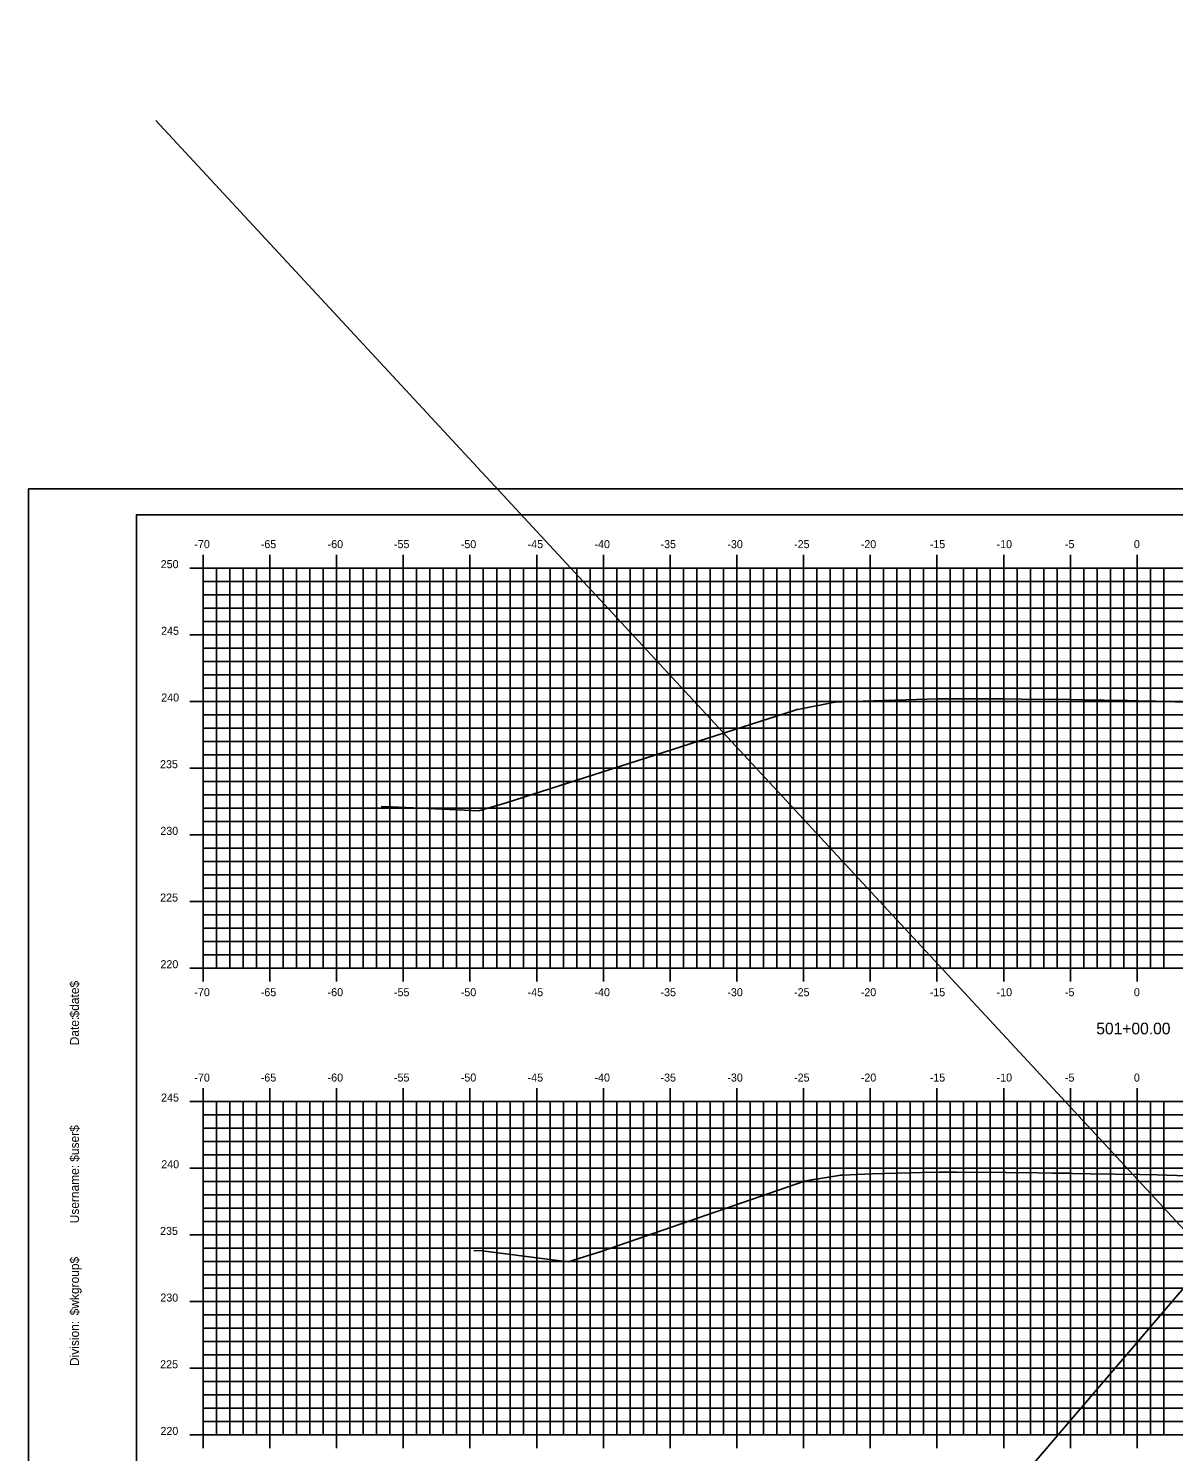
# Model space of a CAD drawing. Extents: x 1170543 to 1177585, y 609599 to 610623.
# Drawn here: x 1170543.4 to 1170629.2, y 610306.6 to 610413.3 of the extents above; entities that cross this region are included whole.
import ezdxf

# ---------------------------------------------------------------- set-up
doc = ezdxf.new("R2010")
doc.units = 0
doc.layers.add('Default', color=7, linetype='Continuous')

msp = doc.modelspace()

# ---------------------------------------------------------------- linework, layer by layer
at = {"layer": 'Default'}
for p, q in [((1170710.72, 610413.27), (1170567.59, 610245.89)), ((1170552.93, 610406.37), (1170706.4, 610240.71)), ((1170556.47, 610373.8), (1170556.47, 610372.8)), ((1170561.47, 610373.8), (1170561.47, 610372.8)), ((1170566.47, 610373.8), (1170566.47, 610372.8)), ((1170571.47, 610373.8), (1170571.47, 610372.8)), ((1170576.47, 610373.8), (1170576.47, 610372.8)), ((1170581.47, 610373.8), (1170581.47, 610372.8)), ((1170586.47, 610373.8), (1170586.47, 610372.8)), ((1170591.47, 610373.8), (1170591.47, 610372.8)), ((1170596.47, 610373.8), (1170596.47, 610372.8)), ((1170601.47, 610373.8), (1170601.47, 610372.8)), ((1170606.47, 610373.8), (1170606.47, 610372.8)), ((1170611.47, 610373.8), (1170611.47, 610372.8)), ((1170616.47, 610373.8), (1170616.47, 610372.8)), ((1170621.47, 610373.8), (1170621.47, 610372.8)), ((1170626.47, 610373.8), (1170626.47, 610372.8)), ((1170555.47, 610372.8), (1170556.47, 610372.8)), ((1170556.47, 610372.8), (1170696.47, 610372.8)), ((1170556.47, 610342.8), (1170556.47, 610372.8)), ((1170556.47, 610342.8), (1170556.47, 610372.8)), ((1170556.47, 610372.8), (1170696.47, 610372.8)), ((1170557.47, 610342.8), (1170557.47, 610372.8)), ((1170558.47, 610342.8), (1170558.47, 610372.8)), ((1170559.47, 610342.8), (1170559.47, 610372.8)), ((1170560.47, 610342.8), (1170560.47, 610372.8)), ((1170561.47, 610342.8), (1170561.47, 610372.8)), ((1170562.47, 610342.8), (1170562.47, 610372.8)), ((1170563.47, 610342.8), (1170563.47, 610372.8)), ((1170564.47, 610342.8), (1170564.47, 610372.8)), ((1170565.47, 610342.8), (1170565.47, 610372.8)), ((1170566.47, 610342.8), (1170566.47, 610372.8)), ((1170567.47, 610342.8), (1170567.47, 610372.8)), ((1170568.47, 610342.8), (1170568.47, 610372.8)), ((1170569.47, 610342.8), (1170569.47, 610372.8)), ((1170570.47, 610342.8), (1170570.47, 610372.8)), ((1170571.47, 610342.8), (1170571.47, 610372.8)), ((1170572.47, 610342.8), (1170572.47, 610372.8)), ((1170573.47, 610342.8), (1170573.47, 610372.8)), ((1170574.47, 610342.8), (1170574.47, 610372.8)), ((1170575.47, 610342.8), (1170575.47, 610372.8)), ((1170576.47, 610342.8), (1170576.47, 610372.8)), ((1170577.47, 610342.8), (1170577.47, 610372.8)), ((1170578.47, 610342.8), (1170578.47, 610372.8)), ((1170579.47, 610342.8), (1170579.47, 610372.8)), ((1170580.47, 610342.8), (1170580.47, 610372.8)), ((1170581.47, 610342.8), (1170581.47, 610372.8)), ((1170582.47, 610342.8), (1170582.47, 610372.8)), ((1170583.47, 610342.8), (1170583.47, 610372.8)), ((1170584.47, 610342.8), (1170584.47, 610372.8)), ((1170585.47, 610342.8), (1170585.47, 610372.8)), ((1170586.47, 610342.8), (1170586.47, 610372.8)), ((1170587.47, 610342.8), (1170587.47, 610372.8)), ((1170588.47, 610342.8), (1170588.47, 610372.8)), ((1170589.47, 610342.8), (1170589.47, 610372.8)), ((1170590.47, 610342.8), (1170590.47, 610372.8)), ((1170591.47, 610342.8), (1170591.47, 610372.8)), ((1170592.47, 610342.8), (1170592.47, 610372.8)), ((1170593.47, 610342.8), (1170593.47, 610372.8)), ((1170594.47, 610342.8), (1170594.47, 610372.8)), ((1170595.47, 610342.8), (1170595.47, 610372.8)), ((1170596.47, 610342.8), (1170596.47, 610372.8)), ((1170597.47, 610342.8), (1170597.47, 610372.8)), ((1170598.47, 610342.8), (1170598.47, 610372.8)), ((1170599.47, 610342.8), (1170599.47, 610372.8)), ((1170600.47, 610342.8), (1170600.47, 610372.8)), ((1170601.47, 610342.8), (1170601.47, 610372.8)), ((1170602.47, 610342.8), (1170602.47, 610372.8)), ((1170603.47, 610342.8), (1170603.47, 610372.8)), ((1170604.47, 610342.8), (1170604.47, 610372.8)), ((1170605.47, 610342.8), (1170605.47, 610372.8)), ((1170606.47, 610342.8), (1170606.47, 610372.8)), ((1170607.47, 610342.8), (1170607.47, 610372.8)), ((1170608.47, 610342.8), (1170608.47, 610372.8)), ((1170609.47, 610342.8), (1170609.47, 610372.8)), ((1170610.47, 610342.8), (1170610.47, 610372.8)), ((1170611.47, 610342.8), (1170611.47, 610372.8)), ((1170612.47, 610342.8), (1170612.47, 610372.8)), ((1170613.47, 610342.8), (1170613.47, 610372.8)), ((1170614.47, 610342.8), (1170614.47, 610372.8)), ((1170615.47, 610342.8), (1170615.47, 610372.8)), ((1170616.47, 610342.8), (1170616.47, 610372.8)), ((1170617.47, 610342.8), (1170617.47, 610372.8)), ((1170618.47, 610342.8), (1170618.47, 610372.8)), ((1170619.47, 610342.8), (1170619.47, 610372.8)), ((1170620.47, 610342.8), (1170620.47, 610372.8)), ((1170621.47, 610342.8), (1170621.47, 610372.8)), ((1170622.47, 610342.8), (1170622.47, 610372.8)), ((1170623.47, 610342.8), (1170623.47, 610372.8)), ((1170624.47, 610342.8), (1170624.47, 610372.8)), ((1170625.47, 610342.8), (1170625.47, 610372.8)), ((1170626.47, 610342.8), (1170626.47, 610372.8)), ((1170627.47, 610342.8), (1170627.47, 610372.8)), ((1170628.47, 610342.8), (1170628.47, 610372.8)), ((1170556.47, 610371.8), (1170696.47, 610371.8)), ((1170556.47, 610371.8), (1170557.47, 610371.8)), ((1170556.47, 610370.8), (1170696.47, 610370.8)), ((1170556.47, 610370.8), (1170557.47, 610370.8)), ((1170556.47, 610369.8), (1170696.47, 610369.8)), ((1170556.47, 610369.8), (1170557.47, 610369.8)), ((1170556.47, 610368.8), (1170696.47, 610368.8)), ((1170556.47, 610368.8), (1170557.47, 610368.8)), ((1170555.47, 610367.8), (1170556.47, 610367.8)), ((1170556.47, 610367.8), (1170696.47, 610367.8)), ((1170556.47, 610366.8), (1170696.47, 610366.8)), ((1170556.47, 610366.8), (1170557.47, 610366.8)), ((1170556.47, 610365.8), (1170696.47, 610365.8)), ((1170556.47, 610365.8), (1170557.47, 610365.8)), ((1170556.47, 610364.8), (1170696.47, 610364.8)), ((1170556.47, 610364.8), (1170557.47, 610364.8)), ((1170556.47, 610363.8), (1170696.47, 610363.8)), ((1170556.47, 610363.8), (1170557.47, 610363.8)), ((1170555.47, 610362.8), (1170556.47, 610362.8)), ((1170556.47, 610362.8), (1170696.47, 610362.8)), ((1170556.47, 610361.8), (1170696.47, 610361.8)), ((1170556.47, 610361.8), (1170557.47, 610361.8)), ((1170556.47, 610360.8), (1170696.47, 610360.8)), ((1170556.47, 610360.8), (1170557.47, 610360.8)), ((1170556.47, 610359.8), (1170696.47, 610359.8)), ((1170556.47, 610359.8), (1170557.47, 610359.8)), ((1170556.47, 610358.8), (1170696.47, 610358.8)), ((1170556.47, 610358.8), (1170557.47, 610358.8)), ((1170555.47, 610357.8), (1170556.47, 610357.8)), ((1170556.47, 610357.8), (1170696.47, 610357.8)), ((1170556.47, 610356.8), (1170696.47, 610356.8)), ((1170556.47, 610356.8), (1170557.47, 610356.8)), ((1170556.47, 610355.8), (1170696.47, 610355.8)), ((1170556.47, 610355.8), (1170557.47, 610355.8)), ((1170556.47, 610354.8), (1170696.47, 610354.8)), ((1170556.47, 610354.8), (1170557.47, 610354.8)), ((1170556.47, 610353.8), (1170696.47, 610353.8)), ((1170556.47, 610353.8), (1170557.47, 610353.8)), ((1170555.47, 610352.8), (1170556.47, 610352.8)), ((1170556.47, 610352.8), (1170696.47, 610352.8)), ((1170556.47, 610351.8), (1170696.47, 610351.8)), ((1170556.47, 610351.8), (1170557.47, 610351.8)), ((1170556.47, 610350.8), (1170696.47, 610350.8)), ((1170556.47, 610350.8), (1170557.47, 610350.8)), ((1170556.47, 610349.8), (1170696.47, 610349.8)), ((1170556.47, 610349.8), (1170557.47, 610349.8)), ((1170555.47, 610347.8), (1170556.47, 610347.8)), ((1170556.47, 610348.8), (1170696.47, 610348.8)), ((1170556.47, 610348.8), (1170557.47, 610348.8)), ((1170556.47, 610347.8), (1170696.47, 610347.8)), ((1170556.47, 610346.8), (1170696.47, 610346.8)), ((1170556.47, 610346.8), (1170557.47, 610346.8)), ((1170556.47, 610345.8), (1170696.47, 610345.8)), ((1170556.47, 610345.8), (1170557.47, 610345.8)), ((1170556.47, 610344.8), (1170696.47, 610344.8)), ((1170556.47, 610344.8), (1170557.47, 610344.8)), ((1170556.47, 610343.8), (1170696.47, 610343.8)), ((1170556.47, 610343.8), (1170557.47, 610343.8)), ((1170555.47, 610342.8), (1170556.47, 610342.8)), ((1170556.47, 610342.8), (1170696.47, 610342.8)), ((1170556.47, 610342.8), (1170696.47, 610342.8)), ((1170556.47, 610341.8), (1170556.47, 610342.8)), ((1170561.47, 610341.8), (1170561.47, 610342.8)), ((1170566.47, 610341.8), (1170566.47, 610342.8)), ((1170571.47, 610341.8), (1170571.47, 610342.8)), ((1170576.47, 610341.8), (1170576.47, 610342.8)), ((1170581.47, 610341.8), (1170581.47, 610342.8)), ((1170586.47, 610341.8), (1170586.47, 610342.8)), ((1170591.47, 610341.8), (1170591.47, 610342.8)), ((1170596.47, 610341.8), (1170596.47, 610342.8)), ((1170601.47, 610341.8), (1170601.47, 610342.8)), ((1170606.47, 610341.8), (1170606.47, 610342.8)), ((1170611.47, 610341.8), (1170611.47, 610342.8)), ((1170616.47, 610341.8), (1170616.47, 610342.8)), ((1170621.47, 610341.8), (1170621.47, 610342.8)), ((1170626.47, 610341.8), (1170626.47, 610342.8)), ((1170556.47, 610333.8), (1170556.47, 610332.8)), ((1170561.47, 610333.8), (1170561.47, 610332.8)), ((1170566.47, 610333.8), (1170566.47, 610332.8)), ((1170571.47, 610333.8), (1170571.47, 610332.8)), ((1170576.47, 610333.8), (1170576.47, 610332.8)), ((1170581.47, 610333.8), (1170581.47, 610332.8)), ((1170586.47, 610333.8), (1170586.47, 610332.8)), ((1170591.47, 610333.8), (1170591.47, 610332.8)), ((1170596.47, 610333.8), (1170596.47, 610332.8)), ((1170601.47, 610333.8), (1170601.47, 610332.8)), ((1170606.47, 610333.8), (1170606.47, 610332.8)), ((1170611.47, 610333.8), (1170611.47, 610332.8)), ((1170616.47, 610333.8), (1170616.47, 610332.8)), ((1170621.47, 610333.8), (1170621.47, 610332.8)), ((1170626.47, 610333.8), (1170626.47, 610332.8)), ((1170555.47, 610332.8), (1170556.47, 610332.8)), ((1170556.47, 610332.8), (1170696.47, 610332.8)), ((1170556.47, 610307.8), (1170556.47, 610332.8)), ((1170556.47, 610307.8), (1170556.47, 610332.8)), ((1170556.47, 610332.8), (1170696.47, 610332.8)), ((1170556.47, 610331.8), (1170696.47, 610331.8)), ((1170556.47, 610331.8), (1170557.47, 610331.8)), ((1170557.47, 610307.8), (1170557.47, 610332.8)), ((1170558.47, 610307.8), (1170558.47, 610332.8)), ((1170559.47, 610307.8), (1170559.47, 610332.8)), ((1170560.47, 610307.8), (1170560.47, 610332.8)), ((1170561.47, 610307.8), (1170561.47, 610332.8)), ((1170562.47, 610307.8), (1170562.47, 610332.8)), ((1170563.47, 610307.8), (1170563.47, 610332.8)), ((1170564.47, 610307.8), (1170564.47, 610332.8)), ((1170565.47, 610307.8), (1170565.47, 610332.8)), ((1170566.47, 610307.8), (1170566.47, 610332.8)), ((1170567.47, 610307.8), (1170567.47, 610332.8)), ((1170568.47, 610307.8), (1170568.47, 610332.8)), ((1170569.47, 610307.8), (1170569.47, 610332.8)), ((1170570.47, 610307.8), (1170570.47, 610332.8)), ((1170571.47, 610307.8), (1170571.47, 610332.8)), ((1170572.47, 610307.8), (1170572.47, 610332.8)), ((1170573.47, 610307.8), (1170573.47, 610332.8)), ((1170574.47, 610307.8), (1170574.47, 610332.8)), ((1170575.47, 610307.8), (1170575.47, 610332.8)), ((1170576.47, 610307.8), (1170576.47, 610332.8)), ((1170577.47, 610307.8), (1170577.47, 610332.8)), ((1170578.47, 610307.8), (1170578.47, 610332.8)), ((1170579.47, 610307.8), (1170579.47, 610332.8)), ((1170580.47, 610307.8), (1170580.47, 610332.8)), ((1170581.47, 610307.8), (1170581.47, 610332.8)), ((1170582.47, 610307.8), (1170582.47, 610332.8)), ((1170583.47, 610307.8), (1170583.47, 610332.8)), ((1170584.47, 610307.8), (1170584.47, 610332.8)), ((1170585.47, 610307.8), (1170585.47, 610332.8)), ((1170586.47, 610307.8), (1170586.47, 610332.8)), ((1170587.47, 610307.8), (1170587.47, 610332.8)), ((1170588.47, 610307.8), (1170588.47, 610332.8)), ((1170589.47, 610307.8), (1170589.47, 610332.8)), ((1170590.47, 610307.8), (1170590.47, 610332.8)), ((1170591.47, 610307.8), (1170591.47, 610332.8)), ((1170592.47, 610307.8), (1170592.47, 610332.8)), ((1170593.47, 610307.8), (1170593.47, 610332.8)), ((1170594.47, 610307.8), (1170594.47, 610332.8)), ((1170595.47, 610307.8), (1170595.47, 610332.8)), ((1170596.47, 610307.8), (1170596.47, 610332.8)), ((1170597.47, 610307.8), (1170597.47, 610332.8)), ((1170598.47, 610307.8), (1170598.47, 610332.8)), ((1170599.47, 610307.8), (1170599.47, 610332.8)), ((1170600.47, 610307.8), (1170600.47, 610332.8)), ((1170601.47, 610307.8), (1170601.47, 610332.8)), ((1170602.47, 610307.8), (1170602.47, 610332.8)), ((1170603.47, 610307.8), (1170603.47, 610332.8)), ((1170604.47, 610307.8), (1170604.47, 610332.8)), ((1170605.47, 610307.8), (1170605.47, 610332.8)), ((1170606.47, 610307.8), (1170606.47, 610332.8)), ((1170607.47, 610307.8), (1170607.47, 610332.8)), ((1170608.47, 610307.8), (1170608.47, 610332.8)), ((1170609.47, 610307.8), (1170609.47, 610332.8)), ((1170610.47, 610307.8), (1170610.47, 610332.8)), ((1170611.47, 610307.8), (1170611.47, 610332.8)), ((1170612.47, 610307.8), (1170612.47, 610332.8)), ((1170613.47, 610307.8), (1170613.47, 610332.8)), ((1170614.47, 610307.8), (1170614.47, 610332.8)), ((1170615.47, 610307.8), (1170615.47, 610332.8)), ((1170616.47, 610307.8), (1170616.47, 610332.8)), ((1170617.47, 610307.8), (1170617.47, 610332.8)), ((1170618.47, 610307.8), (1170618.47, 610332.8)), ((1170619.47, 610307.8), (1170619.47, 610332.8)), ((1170620.47, 610307.8), (1170620.47, 610332.8)), ((1170621.47, 610307.8), (1170621.47, 610332.8)), ((1170622.47, 610307.8), (1170622.47, 610332.8)), ((1170623.47, 610307.8), (1170623.47, 610332.8)), ((1170624.47, 610307.8), (1170624.47, 610332.8)), ((1170625.47, 610307.8), (1170625.47, 610332.8)), ((1170626.47, 610307.8), (1170626.47, 610332.8)), ((1170627.47, 610307.8), (1170627.47, 610332.8)), ((1170628.47, 610307.8), (1170628.47, 610332.8)), ((1170556.47, 610330.8), (1170696.47, 610330.8)), ((1170556.47, 610330.8), (1170557.47, 610330.8)), ((1170556.47, 610329.8), (1170696.47, 610329.8)), ((1170556.47, 610329.8), (1170557.47, 610329.8)), ((1170556.47, 610328.8), (1170696.47, 610328.8)), ((1170556.47, 610328.8), (1170557.47, 610328.8)), ((1170555.47, 610327.8), (1170556.47, 610327.8)), ((1170556.47, 610327.8), (1170696.47, 610327.8)), ((1170556.47, 610326.8), (1170696.47, 610326.8)), ((1170556.47, 610326.8), (1170557.47, 610326.8)), ((1170556.47, 610325.8), (1170696.47, 610325.8)), ((1170556.47, 610325.8), (1170557.47, 610325.8)), ((1170556.47, 610324.8), (1170696.47, 610324.8)), ((1170556.47, 610324.8), (1170557.47, 610324.8)), ((1170556.47, 610323.8), (1170696.47, 610323.8)), ((1170556.47, 610323.8), (1170557.47, 610323.8)), ((1170555.47, 610322.8), (1170556.47, 610322.8)), ((1170556.47, 610322.8), (1170696.47, 610322.8)), ((1170556.47, 610321.8), (1170696.47, 610321.8)), ((1170556.47, 610321.8), (1170557.47, 610321.8)), ((1170556.47, 610320.8), (1170696.47, 610320.8)), ((1170556.47, 610320.8), (1170557.47, 610320.8)), ((1170556.47, 610319.8), (1170696.47, 610319.8)), ((1170556.47, 610319.8), (1170557.47, 610319.8)), ((1170556.47, 610318.8), (1170696.47, 610318.8)), ((1170556.47, 610318.8), (1170557.47, 610318.8)), ((1170555.47, 610317.8), (1170556.47, 610317.8)), ((1170556.47, 610317.8), (1170696.47, 610317.8)), ((1170556.47, 610316.8), (1170696.47, 610316.8)), ((1170556.47, 610316.8), (1170557.47, 610316.8)), ((1170556.47, 610315.8), (1170696.47, 610315.8)), ((1170556.47, 610315.8), (1170557.47, 610315.8)), ((1170556.47, 610314.8), (1170696.47, 610314.8)), ((1170556.47, 610314.8), (1170557.47, 610314.8)), ((1170556.47, 610313.8), (1170696.47, 610313.8)), ((1170556.47, 610313.8), (1170557.47, 610313.8)), ((1170555.47, 610312.8), (1170556.47, 610312.8)), ((1170556.47, 610312.8), (1170696.47, 610312.8)), ((1170556.47, 610311.8), (1170696.47, 610311.8)), ((1170556.47, 610311.8), (1170557.47, 610311.8)), ((1170556.47, 610310.8), (1170696.47, 610310.8)), ((1170556.47, 610310.8), (1170557.47, 610310.8)), ((1170556.47, 610309.8), (1170696.47, 610309.8)), ((1170556.47, 610309.8), (1170557.47, 610309.8)), ((1170556.47, 610308.8), (1170696.47, 610308.8)), ((1170556.47, 610308.8), (1170557.47, 610308.8)), ((1170555.47, 610307.8), (1170556.47, 610307.8)), ((1170556.47, 610307.8), (1170696.47, 610307.8)), ((1170556.47, 610307.8), (1170696.47, 610307.8)), ((1170556.47, 610306.8), (1170556.47, 610307.8)), ((1170561.47, 610306.8), (1170561.47, 610307.8)), ((1170566.47, 610306.8), (1170566.47, 610307.8)), ((1170571.47, 610306.8), (1170571.47, 610307.8)), ((1170576.47, 610306.8), (1170576.47, 610307.8)), ((1170581.47, 610306.8), (1170581.47, 610307.8)), ((1170586.47, 610306.8), (1170586.47, 610307.8)), ((1170591.47, 610306.8), (1170591.47, 610307.8)), ((1170596.47, 610306.8), (1170596.47, 610307.8)), ((1170601.47, 610306.8), (1170601.47, 610307.8)), ((1170606.47, 610306.8), (1170606.47, 610307.8)), ((1170611.47, 610306.8), (1170611.47, 610307.8)), ((1170616.47, 610306.8), (1170616.47, 610307.8)), ((1170621.47, 610306.8), (1170621.47, 610307.8)), ((1170626.47, 610306.8), (1170626.47, 610307.8))]:
    msp.add_line(p, q, dxfattribs=at)
for points in [[(1170543.38, 610268.74), (1170713.38, 610268.74), (1170713.38, 610378.74), (1170543.38, 610378.74)], [(1170551.47, 610271.8), (1170711.47, 610271.8), (1170711.47, 610376.8), (1170551.47, 610376.8)]]:
    msp.add_lwpolyline(points, close=True, dxfattribs=at)
for points in [[(1170569.82, 610354.93), (1170570.55, 610354.9), (1170577.13, 610354.61), (1170579.19, 610355.21), (1170600.83, 610362.16), (1170600.97, 610362.19), (1170601.06, 610362.21), (1170601.28, 610362.25), (1170603.69, 610362.72), (1170603.98, 610362.77), (1170604.35, 610362.78), (1170611.54, 610363.01), (1170612.81, 610363), (1170616.54, 610362.99), (1170617.83, 610362.98), (1170621.54, 610362.94), (1170622.56, 610362.92), (1170625.47, 610362.88), (1170625.76, 610362.87), (1170626.54, 610362.86), (1170627.86, 610362.82), (1170631.54, 610362.71)], [(1170576.76, 610321.64), (1170577.38, 610321.61), (1170583.83, 610320.77), (1170586.3, 610321.56), (1170601.55, 610326.83), (1170602.2, 610326.95), (1170602.56, 610327.01), (1170604.12, 610327.26), (1170604.22, 610327.27), (1170604.37, 610327.28), (1170606.64, 610327.39), (1170610.34, 610327.48), (1170611.64, 610327.51), (1170612.95, 610327.5), (1170616.64, 610327.47), (1170619.05, 610327.45), (1170620.12, 610327.44), (1170621.39, 610327.42), (1170621.64, 610327.41), (1170622.96, 610327.39), (1170626.64, 610327.34), (1170627.97, 610327.3), (1170631.64, 610327.19)]]:
    msp.add_lwpolyline(points, dxfattribs=at)

# ---------------------------------------------------------------- texts
for s, height, p in [('-70', 0.6, (1170555.81, 610374.3)), ('-65', 0.6, (1170560.79, 610374.3)), ('-60', 0.6, (1170565.8, 610374.3)), ('-55', 0.6, (1170570.77, 610374.3)), ('-50', 0.6, (1170575.78, 610374.3)), ('-45', 0.6, (1170580.79, 610374.3)), ('-40', 0.6, (1170585.8, 610374.3)), ('-35', 0.6, (1170590.75, 610374.3)), ('-30', 0.6, (1170595.76, 610374.3)), ('-25', 0.6, (1170600.76, 610374.3)), ('-20', 0.6, (1170605.76, 610374.3)), ('-15', 0.6, (1170610.93, 610374.3)), ('-10', 0.6, (1170615.94, 610374.3)), ('-5', 0.6, (1170621.06, 610374.3)), ('0', 0.6, (1170626.23, 610374.3)), ('250', 0.6, (1170553.29, 610372.8)), ('245', 0.6, (1170553.32, 610367.8)), ('240', 0.6, (1170553.33, 610362.8)), ('235', 0.6, (1170553.24, 610357.8)), ('230', 0.6, (1170553.26, 610352.8)), ('225', 0.6, (1170553.25, 610347.8)), ('220', 0.6, (1170553.27, 610342.8)), ('-70', 0.6, (1170555.81, 610340.7)), ('-65', 0.6, (1170560.79, 610340.7)), ('-60', 0.6, (1170565.8, 610340.7)), ('-55', 0.6, (1170570.77, 610340.7)), ('-50', 0.6, (1170575.78, 610340.7)), ('-45', 0.6, (1170580.79, 610340.7)), ('-40', 0.6, (1170585.8, 610340.7)), ('-35', 0.6, (1170590.75, 610340.7)), ('-30', 0.6, (1170595.76, 610340.7)), ('-25', 0.6, (1170600.76, 610340.7)), ('-20', 0.6, (1170605.76, 610340.7)), ('-15', 0.6, (1170610.93, 610340.7)), ('-10', 0.6, (1170615.94, 610340.7)), ('-5', 0.6, (1170621.06, 610340.7)), ('0', 0.6, (1170626.23, 610340.7)), ('501+00.00', 0.875, (1170623.41, 610337.84)), ('-70', 0.6, (1170555.81, 610334.3)), ('-65', 0.6, (1170560.79, 610334.3)), ('-60', 0.6, (1170565.8, 610334.3)), ('-55', 0.6, (1170570.77, 610334.3)), ('-50', 0.6, (1170575.78, 610334.3)), ('-45', 0.6, (1170580.79, 610334.3)), ('-40', 0.6, (1170585.8, 610334.3)), ('-35', 0.6, (1170590.75, 610334.3)), ('-30', 0.6, (1170595.76, 610334.3)), ('-25', 0.6, (1170600.76, 610334.3)), ('-20', 0.6, (1170605.76, 610334.3)), ('-15', 0.6, (1170610.93, 610334.3)), ('-10', 0.6, (1170615.94, 610334.3)), ('-5', 0.6, (1170621.06, 610334.3)), ('0', 0.6, (1170626.23, 610334.3)), ('245', 0.6, (1170553.32, 610332.8)), ('240', 0.6, (1170553.33, 610327.8)), ('235', 0.6, (1170553.24, 610322.8)), ('230', 0.6, (1170553.26, 610317.8)), ('225', 0.6, (1170553.25, 610312.8)), ('220', 0.6, (1170553.27, 610307.8))]:
    msp.add_text(s, height=height, dxfattribs=at).set_placement(p)
for s, p in [('$date$', (1170547.16, 610339.11)), ('Date:', (1170547.16, 610337.02)), ('$user$', (1170547.16, 610328.29)), ('Username:', (1170547.16, 610323.67)), ('$wkgroup$', (1170547.16, 610316.77)), ('Division:', (1170547.16, 610312.97))]:
    msp.add_text(s, height=0.67, rotation=90, dxfattribs=at).set_placement(p)

doc.saveas('drawing.dxf')
